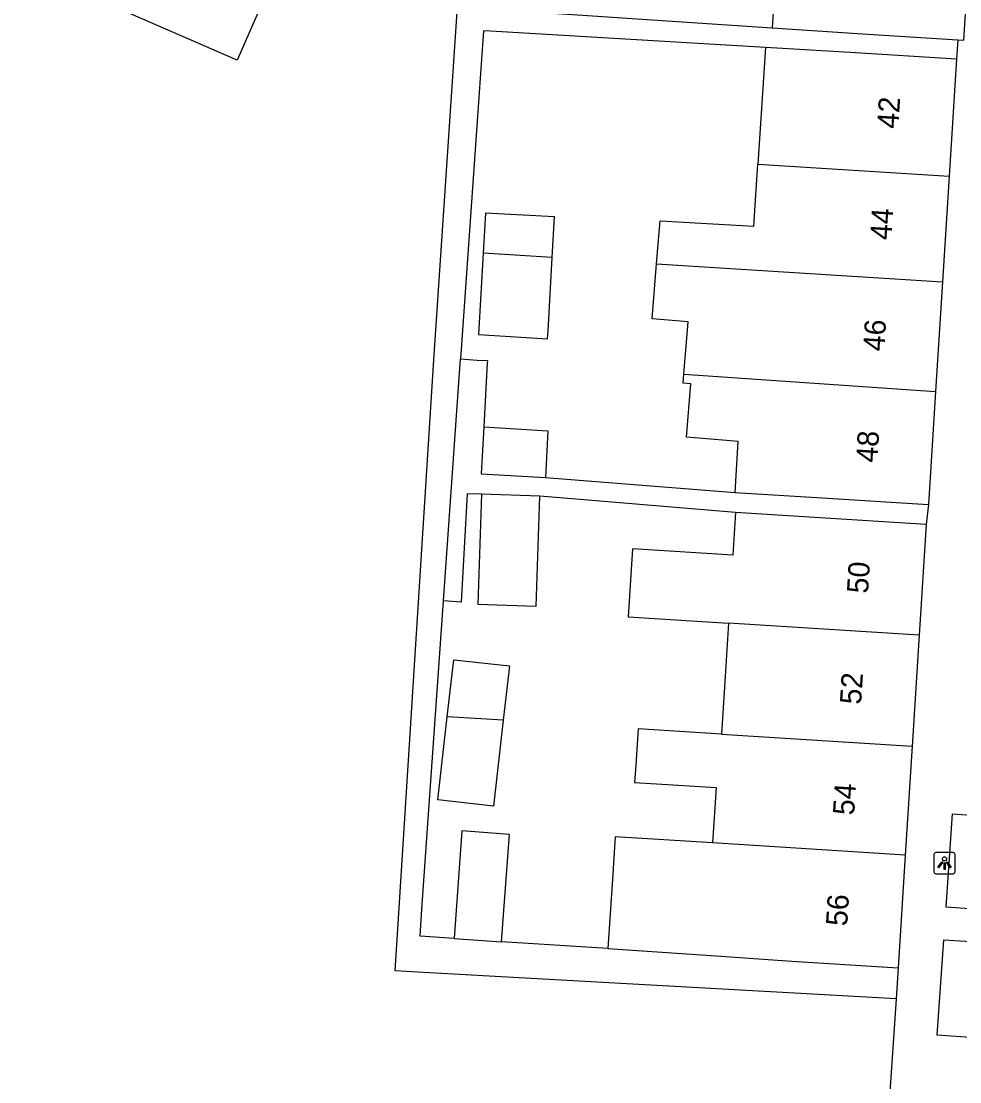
# Model space of a CAD drawing. Extents: x 160356 to 161355, y 381727 to 382845.
# Drawn here: x 160480.48 to 160524.54, y 382065.85 to 382115.63 of the extents above; entities that cross this region are included whole.
import ezdxf

# ---------------------------------------------------------------- set-up
doc = ezdxf.new("R2010")
doc.units = 0
for name, color, linetype in [('IMGEO_Lichtpunt', 7, 'Continuous'), ('IMGEO_Pand', 7, 'Continuous'), ('IMGEO_Pand_nummerreeks', 7, 'Continuous'), ('IMGEO_Voetpad_open', 7, 'Continuous')]:
    doc.layers.add(name, color=color, linetype=linetype)

msp = doc.modelspace()

# ---------------------------------------------------------------- linework, layer by layer
at = {"layer": 'IMGEO_Lichtpunt'}
for p, q in [((160523.328, 382076.52), (160523.328, 382075.713)), ((160523.328, 382076.52), (160523.328, 382075.713)), ((160524.23, 382076.615), (160523.422, 382076.615)), ((160524.23, 382076.615), (160523.422, 382076.615)), ((160524.324, 382075.713), (160524.324, 382076.52)), ((160524.324, 382075.713), (160524.324, 382076.52)), ((160523.422, 382075.619), (160524.23, 382075.619)), ((160523.422, 382075.619), (160524.23, 382075.619))]:
    msp.add_line(p, q, dxfattribs=at)
for points in [[(160523.702, 382076.184), (160523.741, 382076.156), (160523.553, 382075.894), (160523.515, 382075.921), (160523.702, 382076.184)], [(160523.804, 382076.136), (160523.851, 382076.136), (160523.851, 382075.814), (160523.804, 382075.814), (160523.804, 382076.136)], [(160523.914, 382076.156), (160523.952, 382076.183), (160524.139, 382075.921), (160524.1, 382075.893), (160523.914, 382076.156)]]:
    msp.add_lwpolyline(points, dxfattribs=at)
msp.add_circle((160523.827, 382076.318), 0.0994, dxfattribs=at)
for centre, start, end in [((160523.422, 382076.52), 90, 180), ((160523.422, 382076.52), 90, 180), ((160524.23, 382076.52), 0, 90), ((160524.23, 382076.52), 0, 90), ((160523.422, 382075.713), 180, 270), ((160523.422, 382075.713), 180, 270), ((160524.23, 382075.713), 270, 0), ((160524.23, 382075.713), 270, 360)]:
    msp.add_arc(centre, 0.0946, start, end, dxfattribs=at)
at = {"layer": 'IMGEO_Pand'}
for points in [[(160478.523, 382165.202), (160494.77, 382158.105), (160493.372, 382154.907), (160500, 382152.011), (160503.076, 382150.667), (160500, 382143.518), (160498.974, 382141.133), (160500, 382140.69), (160502.101, 382139.783), (160500, 382134.963), (160497.909, 382130.166), (160500, 382129.257), (160500.99, 382128.826), (160500, 382126.562), (160497.983, 382121.949), (160494.799, 382123.342), (160490.627, 382113.804), (160483.82, 382116.781), (160485.098, 382119.701), (160479.101, 382122.324)], [(160524.717, 382120.755), (160520.122, 382121.044), (160517.634, 382121.199), (160517.73, 382122.642), (160513.499, 382125.419), (160511.676, 382122.468), (160516.039, 382119.822), (160515.739, 382115.319)], [(160524.448, 382114.756), (160524.735, 382114.738), (160525.112, 382120.73), (160524.717, 382120.755)], [(160515.739, 382115.319), (160519.745, 382115.053), (160524.448, 382114.756)], [(160515.42, 382114.399), (160515.065, 382108.931)], [(160524.387, 382113.848), (160519.397, 382114.163), (160515.42, 382114.399)], [(160524.387, 382113.848), (160524.04, 382108.368)], [(160510.31, 382104.242), (160510.477, 382106.271), (160514.876, 382106.006), (160515.065, 382108.931)], [(160515.065, 382108.931), (160524.04, 382108.368)], [(160524.04, 382108.368), (160523.728, 382103.398)], [(160505.409, 382104.55), (160505.514, 382106.445), (160502.271, 382106.625), (160502.167, 382104.754)], [(160502.167, 382104.754), (160501.955, 382100.926), (160505.196, 382100.722), (160505.217, 382101.094), (160505.409, 382104.55)], [(160505.409, 382104.55), (160502.167, 382104.754)], [(160511.588, 382099.063), (160511.791, 382101.526), (160510.097, 382101.666), (160510.31, 382104.242)], [(160510.31, 382104.242), (160523.728, 382103.398)], [(160523.728, 382103.398), (160523.403, 382098.257)], [(160513.997, 382093.518), (160514.148, 382095.914), (160512.1, 382096.083), (160511.718, 382096.115), (160511.924, 382098.611), (160511.553, 382098.642), (160511.588, 382099.063)], [(160511.588, 382099.063), (160523.403, 382098.257)], [(160523.403, 382098.257), (160523.069, 382092.946)], [(160502.198, 382096.598), (160502.075, 382094.389), (160505.091, 382094.222)], [(160502.198, 382096.598), (160505.212, 382096.408), (160505.091, 382094.222)], [(160502.091, 382093.436), (160501.921, 382088.271), (160504.659, 382088.181), (160504.829, 382093.346)], [(160504.829, 382093.346), (160502.091, 382093.436)], [(160513.997, 382093.518), (160518.079, 382093.261), (160523.069, 382092.946)], [(160514.015, 382092.58), (160513.889, 382090.572), (160509.186, 382090.87), (160508.984, 382087.673), (160513.687, 382087.376)], [(160522.968, 382092.016), (160517.978, 382092.33), (160514.015, 382092.58)], [(160522.968, 382092.016), (160522.64, 382086.81)], [(160513.687, 382087.376), (160513.529, 382084.874), (160513.359, 382082.176)], [(160522.64, 382086.81), (160513.687, 382087.376)], [(160522.64, 382086.81), (160522.312, 382081.61)], [(160500.485, 382082.989), (160500.788, 382085.666), (160503.401, 382085.371), (160503.113, 382082.823)], [(160503.113, 382082.823), (160502.658, 382078.796), (160500.044, 382079.092), (160500.485, 382082.989)], [(160503.113, 382082.823), (160500.485, 382082.989)], [(160513.359, 382082.176), (160509.44, 382082.424), (160509.332, 382080.713), (160509.281, 382079.903), (160511.066, 382079.791), (160513.101, 382079.663), (160512.938, 382077.062)], [(160513.359, 382082.176), (160522.312, 382081.61)], [(160522.312, 382081.61), (160521.987, 382076.49)], [(160503.035, 382072.421), (160503.401, 382077.464), (160501.167, 382077.626), (160500.801, 382072.583)], [(160512.938, 382077.062), (160508.359, 382077.351), (160508.234, 382075.37), (160508.029, 382072.103)], [(160521.987, 382076.49), (160512.938, 382077.062)], [(160521.987, 382076.49), (160521.657, 382071.207)], [(160500.801, 382072.583), (160503.035, 382072.421)], [(160508.029, 382072.103), (160512.651, 382071.795), (160516.667, 382071.522), (160521.657, 382071.207)]]:
    msp.add_lwpolyline(points, dxfattribs=at)
at = {"layer": 'IMGEO_Voetpad_open'}
for points in [[(160521.557, 382069.746), (160499.089, 382070.994), (160498.044, 382071.06), (160498.23, 382074.017), (160499.854, 382099.744), (160500.957, 382116.304), (160515.739, 382115.319)], [(160515.42, 382114.399), (160502.511, 382115.165), (160502.182, 382115.185), (160501.104, 382099.783)], [(160524.448, 382114.756), (160524.387, 382113.848)], [(160500.309, 382088.428), (160501.104, 382099.783)], [(160501.104, 382099.783), (160501.888, 382099.728), (160502.37, 382099.701), (160502.363, 382099.581), (160502.198, 382096.598)], [(160505.091, 382094.222), (160513.997, 382093.518)], [(160502.091, 382093.436), (160501.414, 382093.458), (160501.133, 382088.37), (160500.309, 382088.428)], [(160514.015, 382092.58), (160504.829, 382093.346)], [(160523.069, 382092.946), (160522.968, 382092.016)], [(160500.801, 382072.583), (160499.208, 382072.694), (160499.296, 382073.949), (160500.309, 382088.428)], [(160525.959, 382078.312), (160525.663, 382073.929), (160523.912, 382074.047), (160524.208, 382078.43), (160525.959, 382078.312)], [(160525.559, 382072.402), (160525.257, 382067.916), (160523.487, 382068.036), (160523.789, 382072.521), (160525.559, 382072.402)], [(160508.029, 382072.103), (160503.035, 382072.421)], [(160521.657, 382071.207), (160521.557, 382069.746)], [(160521.557, 382069.746), (160520.833, 382059.141)]]:
    msp.add_lwpolyline(points, dxfattribs=at)

# ---------------------------------------------------------------- texts
at = {"layer": 'IMGEO_Pand_nummerreeks'}
for s, rotation, p in [('42', 86.3919, (160521.655, 382110.567)), ('44', 86.3906, (160521.326, 382105.344)), ('46', 86.3906, (160520.997, 382100.119)), ('48', 86.3906, (160520.667, 382094.896)), ('50', 86.3963, (160520.238, 382088.752)), ('52', 86.3963, (160519.91, 382083.544)), ('54', 86.3963, (160519.582, 382078.345)), ('56', 86.395, (160519.254, 382073.142))]:
    msp.add_text(s, height=1, rotation=rotation, dxfattribs=at).set_placement(p)

doc.saveas('drawing.dxf')
